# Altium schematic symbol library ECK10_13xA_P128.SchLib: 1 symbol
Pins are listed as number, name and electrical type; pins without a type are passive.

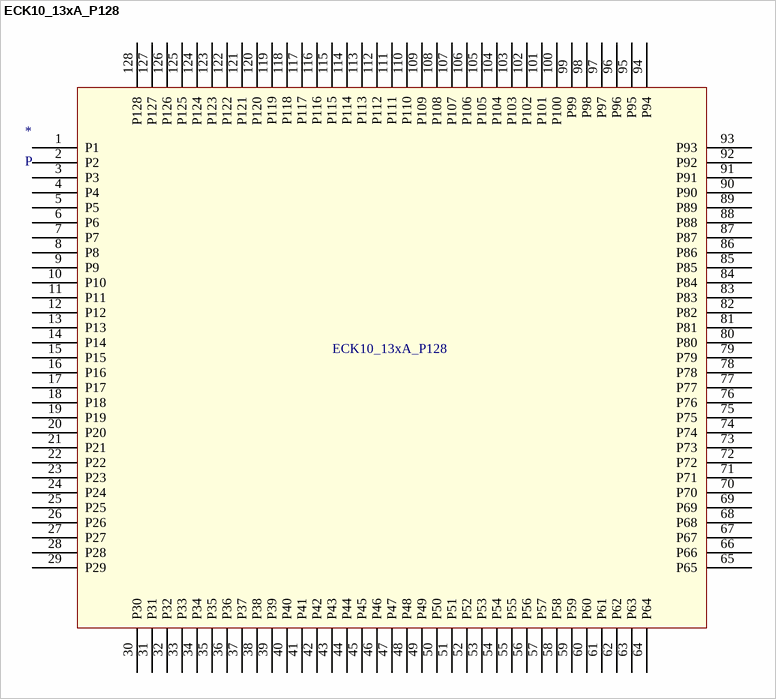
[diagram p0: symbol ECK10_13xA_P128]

## ECK10_13xA_P128
designator *, comment P
pins: 1 P1, 2 P2, 3 P3, 4 P4, 5 P5, 6 P6, 7 P7, 8 P8, 9 P9, 10 P10, 11 P11, 12 P12, 13 P13, 14 P14, 15 P15, 16 P16, 17 P17, 18 P18, 19 P19, 20 P20, 21 P21, 22 P22, 23 P23, 24 P24, 25 P25, 26 P26, 27 P27, 28 P28, 29 P29, 30 P30, 31 P31, 32 P32, 33 P33, 34 P34, 35 P35, 36 P36, 37 P37, 38 P38, 39 P39, 40 P40, 41 P41, 42 P42, 43 P43, 44 P44, 45 P45, 46 P46, 47 P47, 48 P48, 49 P49, 50 P50, 51 P51, 52 P52, 53 P53, 54 P54, 55 P55, 56 P56, 57 P57, 58 P58, 59 P59, 60 P60, 61 P61, 62 P62, 63 P63, 64 P64, 65 P65, 66 P66, 67 P67, 68 P68, 69 P69, 70 P70, 71 P71, 72 P72, 73 P73, 74 P74, 75 P75, 76 P76, 77 P77, 78 P78, 79 P79, 80 P80, 81 P81, 82 P82, 83 P83, 84 P84, 85 P85, 86 P86, 87 P87, 88 P88, 89 P89, 90 P90, 91 P91, 92 P92, 93 P93, 94 P94, 95 P95, 96 P96, 97 P97, 98 P98, 99 P99, 100 P100, 101 P101, 102 P102, 103 P103, 104 P104, 105 P105, 106 P106, 107 P107, 108 P108, 109 P109, 110 P110, 111 P111, 112 P112, 113 P113, 114 P114, 115 P115, 116 P116, 117 P117, 118 P118, 119 P119, 120 P120, 121 P121, 122 P122, 123 P123, 124 P124, 125 P125, 126 P126, 127 P127, 128 P128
